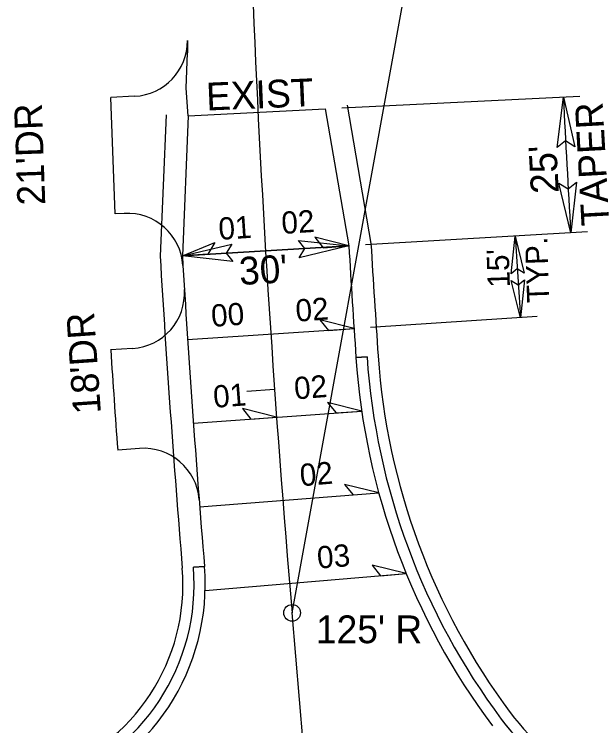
# Model space of a CAD drawing. Extents: x 1755545 to 1761252, y 736169 to 737766.
# Drawn here: x 1758886.8 to 1758991.6, y 737057.4 to 737185.5 of the extents above; entities that cross this region are included whole.
import ezdxf

# ---------------------------------------------------------------- set-up
doc = ezdxf.new("R2010")
doc.units = 0
for name, color, linetype in [('Exist Contamination Potential Cell', 7, 'Continuous'), ('Exist Cultural Church Label', 7, 'Continuous'), ('Old_Level_1', 7, 'Continuous'), ('Prop Dimension', 7, 'Continuous'), ('Prop Horizontal Alignment', 7, 'Continuous'), ('Prop Horizontal Alignment Station Label', 7, 'Continuous'), ('Prop Horizontal Alignment Tick Small', 7, 'Continuous'), ('Prop Paved Shoulder', 7, 'Continuous'), ('Prop Shade Light', 7, 'Continuous'), ('Prop Superelevation Label', 7, 'Continuous'), ('Prop Terminator CELL', 7, 'Continuous'), ('Scratch_Level_4', 7, 'Continuous'), ('Scratch_Level_6', 7, 'Continuous')]:
    doc.layers.add(name, color=color, linetype=linetype)

msp = doc.modelspace()

# ---------------------------------------------------------------- linework, layer by layer
at = {"layer": 'Exist Contamination Potential Cell'}
for p, q in [((1758918.1, 737167.22), (1758942.72, 737168.44)), ((1758942.72, 737168.44), (1758946.97, 737143.78)), ((1758918.1, 737167.22), (1758917.03, 737141.99))]:
    msp.add_line(p, q, dxfattribs=at)
for centre, radius, start, end in [((1761377.64, 737289.03), 2435, 183.41974, 183.89301), ((1761377.64, 737289.03), 2465, 183.41974, 184.72213), ((1759072.97, 737132.19), 125, 183.893, 216.7448), ((1758881.14, 737082.81), 40, 288.6709, 4.7221)]:
    msp.add_arc(centre, radius, start, end, dxfattribs=at)
at = {"layer": 'Exist Cultural Church Label'}
for points in [[(1758917.03, 737141.99), (1758922.88, 737144.38), (1758921.64, 737142.29)], [(1758946.97, 737143.78), (1758940.85, 737145.38), (1758942.36, 737143.47)], [(1758947.91, 737128.9), (1758941.79, 737130.5), (1758943.29, 737128.59)], [(1758949.29, 737114.05), (1758943.16, 737115.62), (1758944.68, 737113.72)], [(1758933.97, 737112.95), (1758927.84, 737114.51), (1758929.36, 737112.62)], [(1758952.36, 737099.34), (1758946.22, 737100.87), (1758947.75, 737098.98)], [(1758957.3, 737084.81), (1758951.15, 737086.3), (1758952.69, 737084.42)]]:
    msp.add_lwpolyline(points, close=True, dxfattribs=at)
at = {"layer": 'Old_Level_1'}
for p, q in [((1758917.95, 737180.75), (1758917.96, 737178.55)), ((1758917.73, 737172.19), (1758917.96, 737178.55)), ((1758917.96, 737178.55), (1758917.96, 737178.55)), ((1758918.1, 737167.22), (1758917.73, 737172.19)), ((1758908.43, 737170.74), (1758904.19, 737170.53)), ((1758904.93, 737149.54), (1758904.19, 737170.53)), ((1758906.59, 737149.63), (1758904.93, 737149.54)), ((1758908.08, 737125.32), (1758904.13, 737125.06)), ((1758909.34, 737107.33), (1758905.4, 737107.04))]:
    msp.add_line(p, q, dxfattribs=at)
for centre, radius, start, end in [((1758907.95, 737180.72), 10, 272.7427, 0.1659), ((1758907.15, 737139.65), 10, 3.4602, 93.2287), ((1758907.42, 737135.3), 10, 273.7925, 3.561), ((1761377.64, 737289.03), 2478.93, 183.79245, 184.21001), ((1758910.07, 737097.36), 10, 4.4415, 94.21)]:
    msp.add_arc(centre, radius, start, end, dxfattribs=at)
at = {"layer": 'Prop Dimension'}
for p, q in [((1758988.56, 737170.71), (1758945.71, 737168.59)), ((1758989.9, 737146.34), (1758949.97, 737143.96)), ((1758946.97, 737143.78), (1758917.03, 737141.99))]:
    msp.add_line(p, q, dxfattribs=at)
msp.add_arc((1761377.64, 737289.03), 2395, 182.83509, 183.41974, dxfattribs=at)
at = {"layer": 'Prop Horizontal Alignment'}
msp.add_line((1758941.91, 737018.28), (1758936.77, 737077.73), dxfattribs=at)
msp.add_arc((1761377.64, 737289.03), 2450, 182.38146, 184.94752, dxfattribs=at)
at = {"layer": 'Prop Horizontal Alignment Station Label'}
msp.add_line((1758936.77, 737077.73), (1758981.45, 737324.34), dxfattribs=at)
msp.add_circle((1758936.77, 737077.73), 1.5, dxfattribs=at)
at = {"layer": 'Prop Horizontal Alignment Tick Small'}
msp.add_line((1758933.62, 737117.94), (1758928.63, 737117.59), dxfattribs=at)
at = {"layer": 'Prop Paved Shoulder'}
for p, q in [((1758948.26, 737123.71), (1758950.25, 737123.84)), ((1758919.01, 737085.94), (1758921, 737086.1))]:
    msp.add_line(p, q, dxfattribs=at)
for centre, radius, start, end in [((1759072.97, 737132.19), 123, 183.893, 216.7448), ((1758881.14, 737082.81), 38, 288.6709, 4.7237), ((1759012.87, 737087.32), 48, 216.7448, 268.3507)]:
    msp.add_arc(centre, radius, start, end, dxfattribs=at)
at = {"layer": 'Prop Shade Light'}
for p, q in [((1758950.25, 737123.84), (1758948.26, 737123.71)), ((1758921, 737086.1), (1758919.01, 737085.94))]:
    msp.add_line(p, q, dxfattribs=at)
for centre, radius, start, end in [((1759072.97, 737132.19), 123, 183.893, 216.7448), ((1759072.97, 737132.19), 125, 183.893, 216.7448), ((1758881.14, 737082.81), 38, 288.6709, 4.7237), ((1758881.14, 737082.81), 40, 288.6709, 4.7221), ((1759012.87, 737087.32), 48, 216.7448, 271.6265)]:
    msp.add_arc(centre, radius, start, end, dxfattribs=at)
at = {"layer": 'Prop Superelevation Label'}
for p, q in [((1758917.03, 737141.99), (1758946.97, 737143.78)), ((1758980.84, 737131.07), (1758950.9, 737129.1)), ((1758917.97, 737126.93), (1758947.91, 737128.9)), ((1758919.01, 737111.87), (1758949.29, 737114.05)), ((1758920.14, 737096.82), (1758952.36, 737099.34)), ((1758921.13, 737081.76), (1758957.3, 737084.81))]:
    msp.add_line(p, q, dxfattribs=at)
msp.add_arc((1761377.64, 737289.03), 2405, 183.41974, 183.77053, dxfattribs=at)
at = {"layer": 'Prop Terminator CELL'}
for points in [[(1758984.47, 737161.5), (1758985.57, 737170.57), (1758987.61, 737161.61), (1758985.96, 737162.68)], [(1758987.91, 737155.24), (1758986.9, 737146.16), (1758984.76, 737155.1), (1758986.43, 737154.05)], [(1758937.9, 737144.79), (1758946.97, 737143.78), (1758938.03, 737141.64), (1758939.09, 737143.31)], [(1758976.16, 737138.76), (1758976.92, 737145.57), (1758978.52, 737138.86), (1758977.27, 737139.65)], [(1758926.1, 737140.98), (1758917.03, 737141.99), (1758925.96, 737144.13), (1758924.91, 737142.46)], [(1758978.56, 737137.68), (1758977.84, 737130.87), (1758976.2, 737137.57), (1758977.45, 737136.78)]]:
    msp.add_lwpolyline(points, close=True, dxfattribs=at)
at = {"layer": 'Scratch_Level_6'}
for p, q in [((1758946.66, 737169.12), (1758950.95, 737144.24)), ((1758914.1, 737167.39), (1758913.02, 737141.95))]:
    msp.add_line(p, q, dxfattribs=at)
for centre, radius, start, end in [((1761377.64, 737289.03), 2431, 183.4145, 183.89301), ((1761377.64, 737289.03), 2469, 183.415, 184.72213), ((1759072.97, 737132.19), 121, 183.893, 216.7448), ((1758881.14, 737082.81), 36, 288.6709, 4.7221), ((1759012.87, 737087.32), 46, 216.7448, 267.0271)]:
    msp.add_arc(centre, radius, start, end, dxfattribs=at)

# ---------------------------------------------------------------- texts
at = {"layer": 'Prop Dimension'}
for s, rotation, p in [('EXIST', 2.4329, (1758921.41, 737168.15)), ('TAPER', 93.1274, (1758993.84, 737147.53)), ("25'", 93.1274, (1758984.76, 737153.34)), ("30'", 3.4197, (1758927.38, 737136.74)), ("125' R", 360, (1758941.06, 737072.27))]:
    msp.add_text(s, height=5, rotation=rotation, dxfattribs=at).set_placement(p)
at = {"layer": 'Prop Superelevation Label'}
for s, rotation, p in [('02', 3.7705, (1758934.98, 737145.92)), ('01', 3.7705, (1758923.66, 737144.86)), ('TYP.', 91.9359, (1758983.06, 737133.61)), ("15'", 91.9359, (1758975.97, 737136.34)), ('02', 4.1213, (1758937.53, 737130.13)), ('00', 4.1213, (1758922.35, 737129.2)), ('02', 4.4721, (1758937.29, 737116.14)), ('01', 4.4721, (1758922.73, 737114.63)), ('02', 4.8229, (1758938.33, 737100.51)), ('03', 4.9475, (1758941.43, 737085.67))]:
    msp.add_text(s, height=4, rotation=rotation, dxfattribs=at).set_placement(p)
at = {"layer": 'Scratch_Level_4'}
for s, rotation, p in [("21'DR", 92.0141, (1758892.38, 737151.18)), ("18'DR", 93.9307, (1758902.39, 737113.67))]:
    msp.add_text(s, height=5, rotation=rotation, dxfattribs=at).set_placement(p)

doc.saveas('drawing.dxf')
